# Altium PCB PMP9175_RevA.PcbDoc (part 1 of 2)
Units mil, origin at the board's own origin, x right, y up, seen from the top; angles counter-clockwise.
Board outline 3600 x 2200 mil, 4 copper layers (Top Layer, MidLayer1, MidLayer2, Bottom Layer), stack 73.2 mil thick; 114 components, 75 nets, 326 pads, 97 vias.
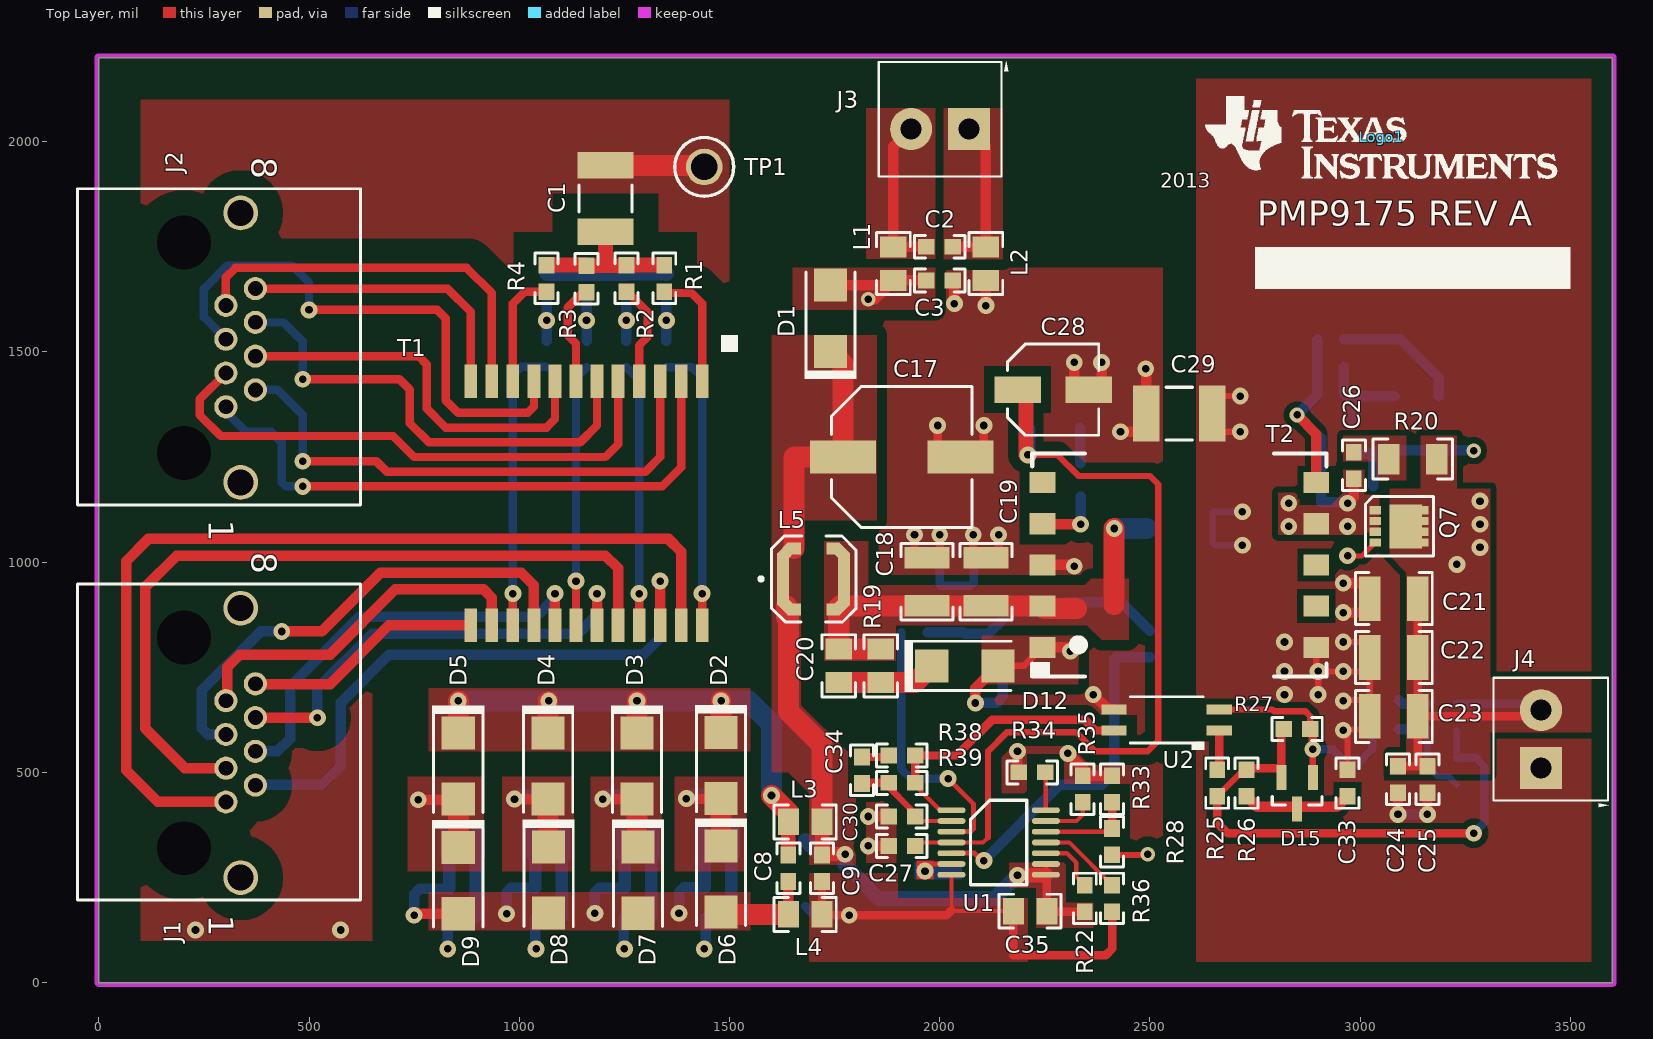
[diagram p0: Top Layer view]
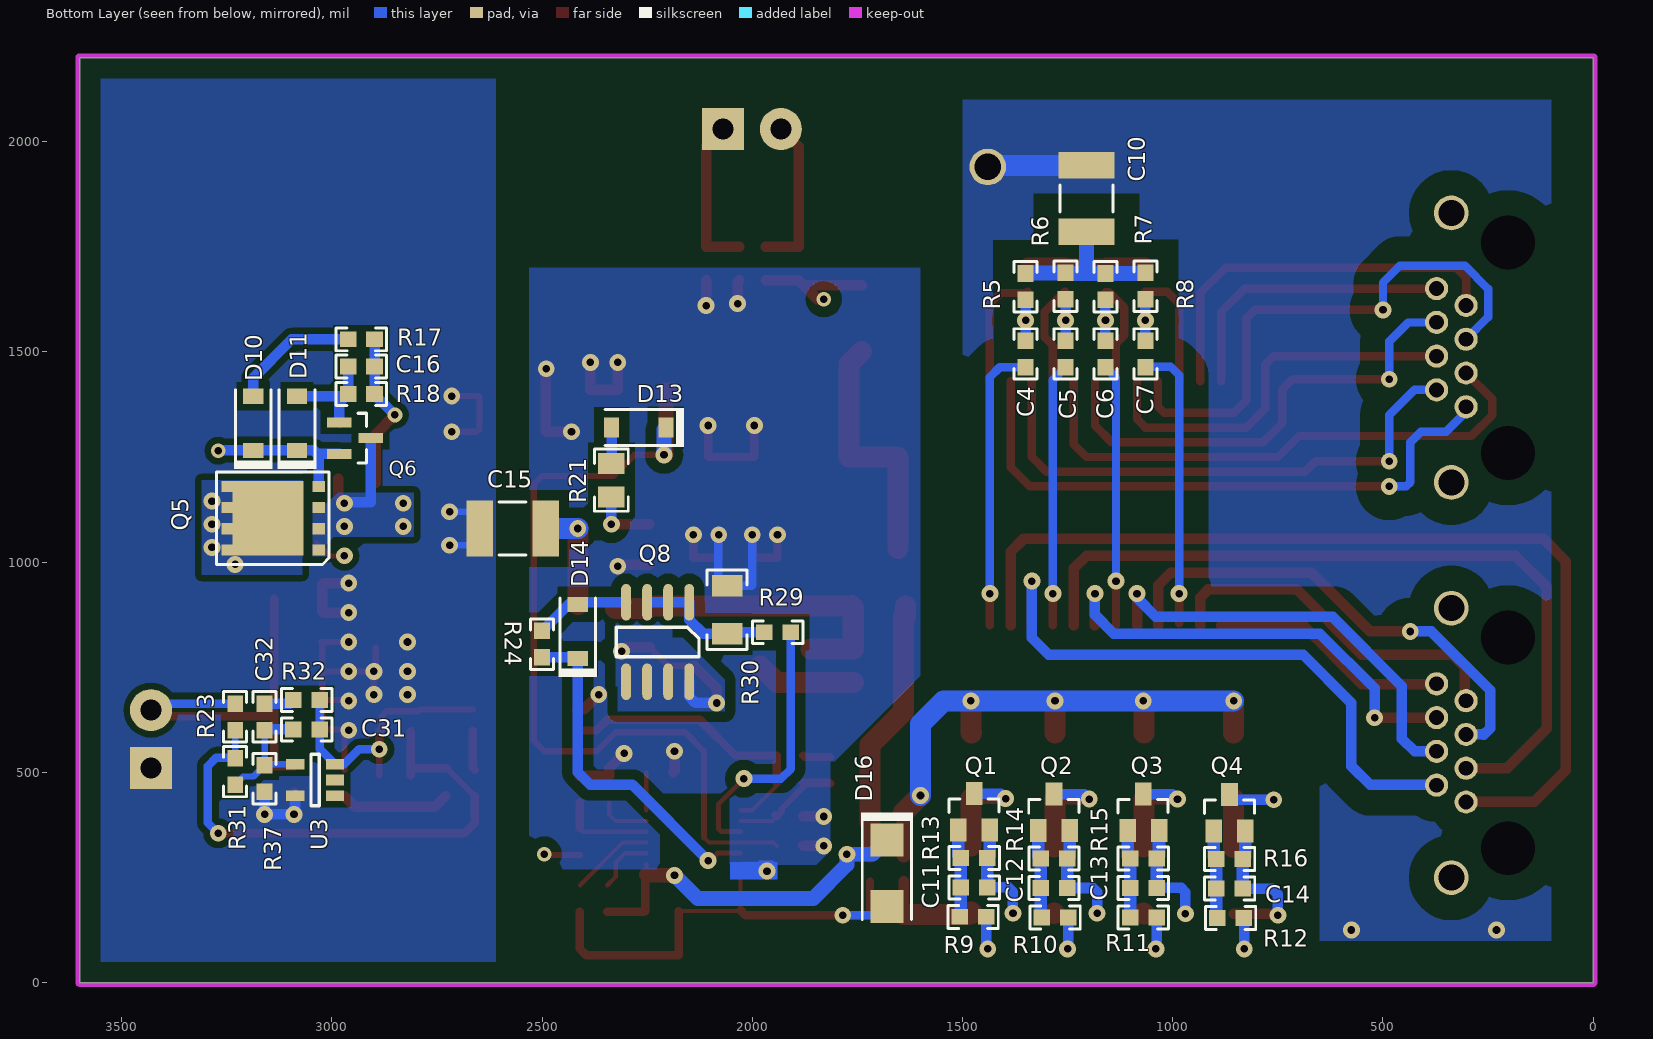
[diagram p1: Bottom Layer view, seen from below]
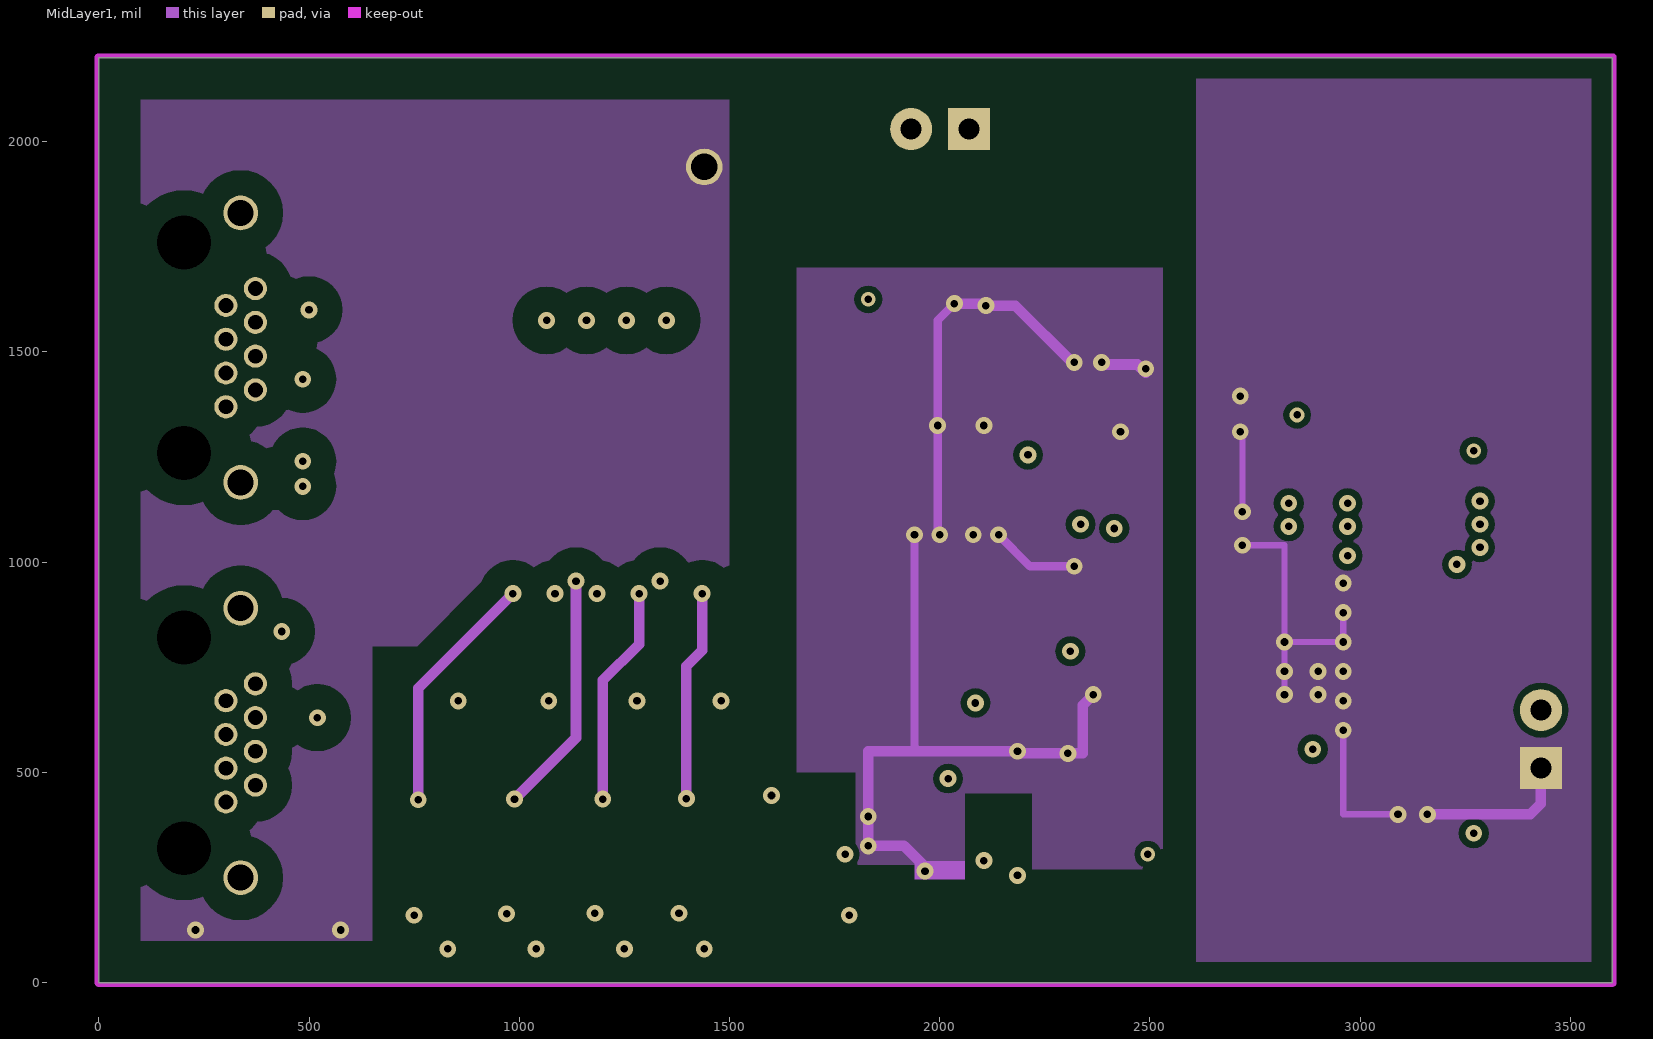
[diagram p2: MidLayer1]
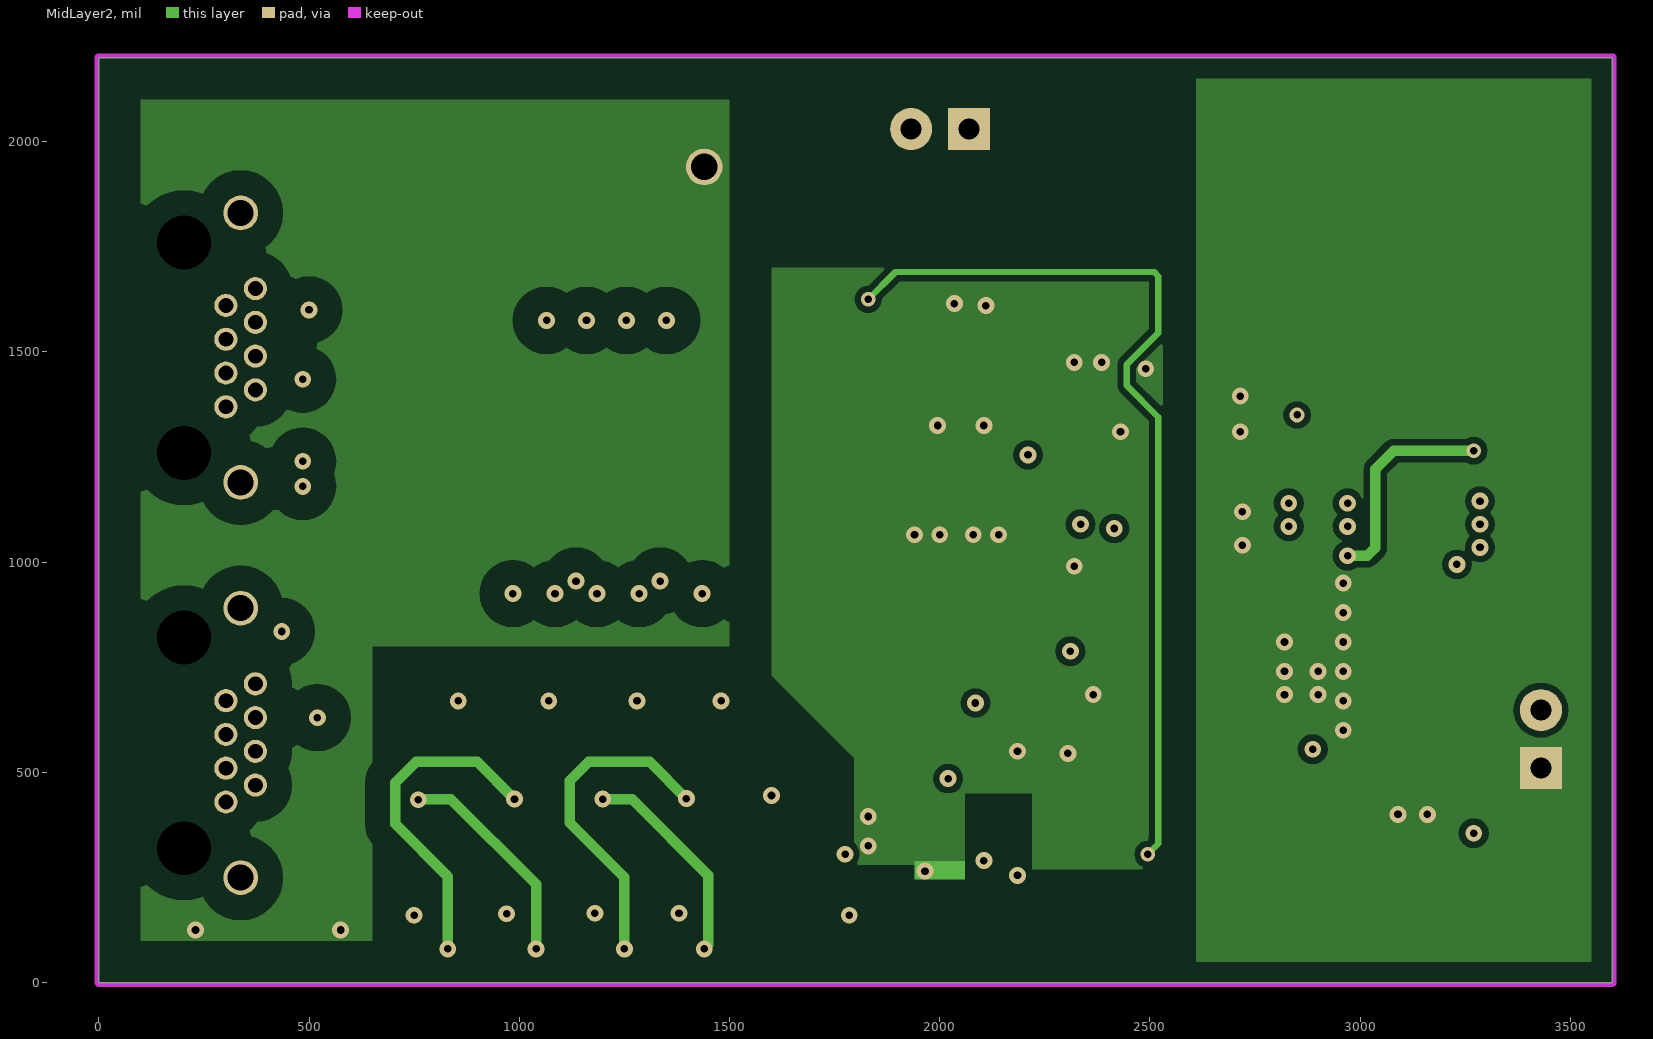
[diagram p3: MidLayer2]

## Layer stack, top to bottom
Top Layer: signal copper 2.8
Dielectric: core 24.7, FR-4, Dk 4.8
MidLayer1: signal copper 2.8
Dielectric: prepreg 12.6, FR-4, Dk 4.8
MidLayer2: signal copper 2.8
Dielectric: core 24.7, FR-4, Dk 4.8
Bottom Layer: signal copper 2.8

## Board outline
0,0 3600,0 3600,2200 0,2200

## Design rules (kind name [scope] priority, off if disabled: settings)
AcuteAngle [All] p1: minimum=4.50000000000000E+0001 checktracksonly=FALSE
AssemblyTestPointUsage [All] p1: valid=2
Clearance Clearance_9 [InNamedPolygon('MidLayer2-EARTH')] p1: gap=60
Clearance Clearance_8 [InNamedPolygon('MidLayer1-EARTH')] p2: gap=60
Clearance Clearance_7 [InNamedPolygon('Bottom Layer-EARTH')] p3: gap=60
Clearance Clearance_6 [InNamedPolygon('Top Layer-EARTH')] p4: gap=60
Clearance Clearance_5 [InNamedPolygon('Bottom Layer-PWRGND')] p5: gap=25
Clearance Clearance_4 [InNamedPolygon('Top Layer-PWRGND')] p6: gap=25
Clearance Clearance_3 [InNamedPolygon('Top Layer-No Net 10')] p7: gap=25
Clearance Clearance_2 [InNamedPolygon('Bottom Layer-EARTH')] p8: gap=60
Clearance Clearance_1 [InNamedPolygon('Top Layer-Earth')] p9: gap=60
Clearance Clearance_BoardEdge_MountingHoles [OnCopper and InComponentClass('Mounting Holes') vs IsKeepOut] p10: gap=25
Clearance Clearance_BoardEdge_Poly [OnCopper and InPoly vs IsKeepOut] p11: gap=25
Clearance Clearance_BoardEdge [OnCopper and Not InComponentClass('Logo') and not InComponentClass('FiducialMark') and not InRegion(1000,500,4000,800) and Not IsKeepout vs IsKeepOut] p12: gap=25
Clearance Clearance_Poly [InPolygon] p13: gap=15
Clearance [All] p14: gap=8
ComponentClearance ComponentClearance_Logo [InComponentClass('Logo')] p1: gap=10 collisioncheckmode=3 verticalgap=10 showdistances=FALSE
ComponentClearance ComponentClearance_ScrewToNut [(HasFootprint('NY PMS 440 0025 PH')) vs (HasFootprint('Keystone_1902C'))] p2: gap=5 collisioncheckmode=3 verticalgap=10 showdistances=FALSE
ComponentClearance ComponentClearance_MountingHoles [InComponentClass('Mounting Holes')] p3: gap=25 collisioncheckmode=3 verticalgap=100000 showdistances=FALSE
ComponentClearance ComponentClearance_SmallPassives [HasFootprint('0201*') or HasFootprint('0402*') or HasFootprint('0508') or HasFootprint('0603*') or HasFootprint('0612') or HasFootprint('0805*') or HasFootprint('0815*') or HasFootprint('0830*') or HasFootprint('1206*') or HasFootprint('1210*') or HasFootprint('1808*') or HasFootprint('1812*') or HasFootprint('1825*') or HasFootprint('2010*') or HasFootprint('2220*') or HasFootprint('2225*') or HasFootprint('2512*') or HasFootprint('2728*') or HasFootprint('3518*') vs HasFootprint('0201*') or HasFootprint('0402*') or HasFootprint('0508') or HasFootprint('0603*') or HasFootprint('0612') or HasFootprint('0805*') or HasFootprint('0815*') or HasFootprint('0830*') or HasFootprint('1206*') or HasFootprint('1210*') or HasFootprint('1808*') or HasFootprint('1812*') or HasFootprint('1825*') or HasFootprint('2010*') or HasFootprint('2220*') or HasFootprint('2225*') or HasFootprint('2512*') or HasFootprint('2728*') or HasFootprint('3518*')] p4: gap=5 collisioncheckmode=3 verticalgap=10 showdistances=FALSE
ComponentClearance ComponentClearance_THtoSMT [IsThruComponent vs IsSMTComponent] p5: gap=10 collisioncheckmode=3 verticalgap=30 showdistances=FALSE
ComponentClearance ComponentClearance_THtoTH [IsThruComponent vs IsThruComponent] p6: gap=10 collisioncheckmode=3 verticalgap=30 showdistances=FALSE
ComponentClearance [All] p7: gap=5 collisioncheckmode=3 verticalgap=10 showdistances=FALSE
DiffPairsRouting [All] p1: maxlimit=100 minlimit=10 mostfreqgap=10 maxuncoupledlength=1000
FabricationTestPointUsage TestPointUsage [All] p1: valid=2 allowmultiple=FALSE
FabricationTestpoint Testpoint [All] p1: side=3 testpointundercomponent=TRUE minsize=40 maxsize=100 preferedsize=60 minholesize=0 maxholesize=40 preferedholesize=32 testpointgrid=1 allowsidetop=TRUE allowsidebottom=TRUE usegrid=TRUE gridtolerance=0.01
FanoutControl Fanout_LCC [IsLCC] p1: bgadir=Out bgaviamode=Centered fanoutstyle=Auto fanoutdirection=Alternating viagrid=1 // Fanout_LCC (Default Rule)
FanoutControl Fanout_BGA [IsBGA] p2: bgadir=Out bgaviamode=Centered fanoutstyle=Auto fanoutdirection=Alternating viagrid=1 // Fanout_BGA (Default Rule)
FanoutControl Fanout_Default [All] p4: bgadir=Out bgaviamode=Centered fanoutstyle=Auto fanoutdirection=Alternating viagrid=1 // Fanout_Default (Default Rule)
FanoutControl Fanout_Small [(CompPinCount < 5)] p5: bgadir=Out bgaviamode=Centered fanoutstyle=Auto fanoutdirection=OutThenIn viagrid=1 // Fanout_Small (Default Rule)
HoleSize [All] p1: absolutevalues=TRUE maxlimit=251 minlimit=6 maxpercent=80.000 minpercent=20.000
MinimumAnnularRing MinimumAnnularRing_ThermalPadVias [IsVia and InAnyComponent] p1: minimumring=5.91
MinimumAnnularRing [All] p2: minimumring=7
MinimumSolderMaskSliver MinimumSolderMaskSliver_Logo [InComponentClass('Logo') vs InComponentClass('Logo')] p1: minsoldermaskwidth=0.7
MinimumSolderMaskSliver [All] p2: minsoldermaskwidth=2
PlaneClearance [All] p1: clearance=12
PlaneConnect [All] p1: planeconnectstyle=Direct reliefexpansion=10 reliefentries=4 reliefconductorwidth=10 reliefairgap=10
PolygonConnect [All] p1: connectstyle=Direct reliefconductorwidth=10 reliefentries=4 polygonreliefangle="90 Angle" airgapwidth=10
RoutingCorners [All] p1: cornerstyle=45-Degree minsetback=0.1 maxsetback=0.2
RoutingVias ThermalPadVias [IsVia and InAnyComponent] p1: holewidth=7.87 width=19.68 viastyle="Through Hole" minholewidth=7.87 minwidth=19.68 maxholewidth=12.99 maxwidth=23.62
RoutingVias [All] p2: holewidth=18 width=35 viastyle="Through Hole" minholewidth=6 minwidth=20 maxholewidth=24 maxwidth=50
SMDToCorner [All] p1: distance=1000
SilkToSilkClearance [All] p1: silktosilkclearance=0.1
SilkscreenOverComponentPads [All] p1: minsilkscreentomaskgap=0.1
SolderMaskExpansion [All] p1: expansion=2
Width [All] p1: maxlimit=100 minlimit=6 preferedwidth=10 checkconnectedcopper=TRUE
12 further rules are at their usual default settings.

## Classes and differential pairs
component class Logo: Logo1
component class PMP9175_RevA_SH1: 40 C1 C2 C3 C4 C5 C6 C7 C8 C9 C10 C11 C12 C13 C14 D1 D2 D3 D4 D5 D6 D7 D8 D9 J1 J2 J3 L1 L2 L3 L4 Logo1 Q1 Q2 Q3 Q4 R1 R2 R3 R4 R5 R6 R7 R8 R9 R10 R11 R12 R13 R14 R15 R16 T1 TP1
component class PMP9175_RevA_SH2: 40 C15 C16 C17 C18 C19 C20 C21 C22 C23 C24 C25 C26 C27 C28 C29 C30 C31 C32 C33 C34 C35 D10 D11 D12 D13 D14 D15 D16 J4 L5 Q5 Q6 Q7 Q8 R17 R18 R19 R20 R21 R22 R23 R24 R25 R26 R27 R28 R29 R30 R31 R32 R33 R34 R35 R36 R37 R38 R39 R40 T2 U1 U2 U3

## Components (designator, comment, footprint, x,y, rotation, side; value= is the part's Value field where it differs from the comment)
C1 "1812GC102KA1" 1812 1205,1865 r90 top
C2 "C1608X7R2A102K" 0603 2000,1750 r0 top
C3 "C1608X7R2A102K" 0603 2000,1670 r0 top
C4 "C1608X7R2A103K" 0603 1350,1495 r90 bottom
C5 "C1608X7R2A103K" 0603 1255,1495 r90 bottom
C6 "C1608X7R2A103K" 0603 1160,1495 r90 bottom
C7 "C1608X7R2A103K" 0603 1065,1495 r90 bottom
C8 "C1608X7R2A102K" 0603 1640,271.95 r270 top
C9 "C1608X7R2A102K" 0603 1720,271.95 r270 top
C10 "1812GC102KA1" 1812 1205,1865 r90 bottom
C11 "C1608C0G1H331J" 0603 1472.45,226.18 r180 bottom
C12 "C1608C0G1H331J" 0603 1282.45,224.92 r180 bottom
C13 "C1608C0G1H331J" 0603 1070,225.08 r180 bottom
C14 "C1608C0G1H331J" 0603 865,223.7 r180 bottom
C15 "C4532X7R3D222K" 1812 2570,1080 r180 bottom
C16 "C1608C0G1H471J" 0603 2930,1465 r180 bottom
C17 "EEE-FK2A220P" SM_RADIAL_F 1910,1250 r0 top
C18 "GRM32ER72A225KA35L" 1210 1969.92,953.23 r90 top
C19 "GRM32ER72A225KA35L" 1210 2109.92,953.23 r90 top
C20 "C2012X7R2A104K" 0805_HV 1759.92,753.23 r270 top
C21 "C3225X5R0J107M" 1210 3080.24,913.23 r180 top
C22 "C3225X5R0J107M" 1210 3080.24,773.23 r180 top
C23 "C3225X5R0J107M" 1210 3080.24,633.23 r180 top
C24 "C1608X7R1C105K" 0603 3089.92,483.23 r270 top
C25 "C1608X7R1H104K" 0603 3159.92,483.23 r270 top
C26 "C1608X7R1H222K" 0603 2985,1230 r270 top
C27 "C1608X7R1C105K" 0603 1910,325 r180 top
C28 "EEE-FK1C220R" SM_RADIAL_C 2270,1410 r0 top
C29 "C4532X7R3D222K" 1812 2569.92,1353.23 r180 top
C30 "C1608X7R1H104K" 0603 1910,395 r180 top
C31 "C1608C0G1H101J" 0603 3059.92,601.93 r180 bottom
C32 "GRM188R71H682KA01D" 0603 3159.92,631.93 r90 bottom
C33 "C1608X7R1C105K" 0603 2969.92,474.53 r90 top
C34 "C1608X7R1E473K" 0603 1815,505 r90 top
C35 "C2012X7R2A104K" 0805_HV 2215,170 r180 top
D1 "B1100-13-F" SMA 1740,1580 r90 top
D2 "B1100-13-F" SMA 1480,516.26 r270 top
D3 "B1100-13-F" SMA 1280,515 r270 top
D4 "B1100-13-F" SMA 1068.7,515.08 r270 top
D5 "B1100-13-F" SMA 855,515 r270 top
D6 "B1100-13-F" SMA 1480,246.26 r270 top
D7 "B1100-13-F" SMA 1282.45,243.62 r270 top
D8 "B1100-13-F" SMA 1070,243.78 r270 top
D9 "B1100-13-F" SMA 855,242.4 r270 top
D10 "MMSD4148T1G" SOD-123 3187.09,1330 r90 bottom
D11 "MMSD4148T1G" SOD-123 3082.78,1330 r90 bottom
D12 "MURA120T3G" SMA 2059.92,753.23 r0 top
D13 "MMSD4148T1G" SOD-123 2270,1320 r0 bottom
D14 "MMSD4148T1G" SOD-123 2415,835 r90 bottom
D15 "BAT54S-7-F" SOT-23 2850,450 r270 top
D16 "SMAJ58A" SMA 1680,260 r270 bottom
J1 "1-406541-1" 1-406541-1 280,570 r270 top
J2 "1-406541-1" 1-406541-1 280,1510 r270 top
J3 "ED555/2DS" TERM_BLK_ED555-2DS 2070,2030 r180 top
J4 "ED555/2DS" TERM_BLK_ED555-2DS 3430,510 r90 top
L1 "MMZ2012R300A" 0805_HV 1890,1710 r270 top
L2 "MMZ2012R300A" 0805_HV 2110,1710 r270 top
L3 "MMZ2012R300A" 0805_HV 1680,381.95 r0 top
L4 "MMZ2012R300A" 0805_HV 1680,161.95 r0 top
L5 "LPS4018-332MLB" LPS4018 1700,960 r0 top
Logo1 "Texas Instruments" TI_Stacked_Overlay_Small 3050,2010 r0 top
Q1 "FDN8601" SSOT-3 1472.45,406.18 r180 bottom
Q2 "FDN8601" SSOT-3 1282.45,404.92 r180 bottom
Q3 "FDN8601" SSOT-3 1070,405 r180 bottom
Q4 "FDN8601" SSOT-3 865,403.7 r180 bottom
Q5 "CSD17527Q5A" TRANS_NexFET_Q5A 3140.35,1104.49 r0 bottom
Q6 "MMBT3906" SOT-23 2945,1295 r180 bottom
Q7 "CSD17551Q3A" TRANS_NexFET_Q3A 3100,1085 r0 top
Q8 "FDS86242" SOIC-8 2225,810 r270 bottom
R1 "CRCW060375R0FKEA" 0603 1345,1675 r90 top
R2 "CRCW060375R0FKEA" 0603 1255,1675 r90 top
R3 "CRCW060375R0FKEA" 0603 1160,1673.7 r90 top
R4 "CRCW060375R0FKEA" 0603 1065,1675 r90 top
R5 "CRCW060375R0FKEA" 0603 1350,1655 r270 bottom
R6 "CRCW060375R0FKEA" 0603 1255,1656.3 r270 bottom
R7 "CRCW060375R0FKEA" 0603 1160,1655 r270 bottom
R8 "CRCW060375R0FKEA" 0603 1065,1656.3 r270 bottom
R9 "CRCW0603499KFKEA" 0603 1475,156.26 r180 bottom
R10 "CRCW0603499KFKEA" 0603 1280,155 r180 bottom
R11 "CRCW0603499KFKEA" 0603 1070,155 r180 bottom
R12 "CRCW0603499KFKEA" 0603 862.55,153.78 r180 bottom
R13 "CRCW0603150KFKEA" 0603 1472.45,296.18 r0 bottom
R14 "CRCW0603150KFKEA" 0603 1282.45,294.92 r0 bottom
R15 "CRCW0603150KFKEA" 0603 1070,295.08 r0 bottom
R16 "CRCW0603150KFKEA" 0603 865,293.7 r0 bottom
R17 "CRCW060310R0JNEA" 0603 2930,1530 r0 bottom
R18 "CRCW06034K99FKEA" 0603 2930,1400 r0 bottom
R19 "CRCW080539K0JNEA" 0805_HV 1859.92,753.23 r90 top
R20 "CRCW12063R30JNEA" 1206 3125.28,1245 r0 top
R21 "CRCW080520R0JNEA" 0805_HV 2335,1195 r270 bottom
R22 "CRCW060327K4FKEA" 0603 2345,200 r270 top
R23 "ERJ-3GEY0R00V" 0603 3229.92,631.93 r90 bottom
R24 "CRCW060310R0JNEA" 0603 2500,805 r90 bottom
R25 "CRCW0603681RFKEA" 0603 2659.92,474.53 r270 top
R26 "CRCW060310K0FKEA" 0603 2729.92,474.53 r90 top
R27 "CRCW06032K00FKEA" 0603 2849.92,603.23 r180 top
R28 "CRCW0603392KFKEA" 0603 2410,335 r270 top
R29 "CRCW06031K00FKEA" 0603 1939.92,833.23 r0 bottom
R30 "STD" 1206 2059.92,886.3 r270 bottom
R31 "CRCW060344K2FKEA" 0603 3229.92,501.93 r90 bottom
R32 "CRCW06031K00FKEA" 0603 3059.92,671.93 r180 bottom
R33 "CRCW060320K5FKEA" 0603 2410,460 r270 top
R34 "CRCW060359K0FKEA" 0603 2220,500 r0 top
R35 "CRCW060380K6FKEA" 0603 2340,460 r270 top
R36 "CRCW060390R9FKEA" 0603 2410,200 r90 top
R37 "CRCW060314K3FKEA" 0603 3159.92,485 r90 bottom
R38 "CRCW06031K00FKEA" 0603 1910,540 r180 top
R39 "CRCW06032K00FKEA" 0603 1910,475 r180 top
T1 "H6062" S0-24_500MIL 1160,1140 r270 top
T2 "PA6340-AL" Coilcraft_PA6340-AL 2569.92,993.23 r90 top
TP1 "5012" Keystone5012 1440,1940 r90 top
U1 "TPS23753APW" PW0014A_N 2140.24,333.23 r0 top
U2 "HMHA2801A" MFP04A 2539.92,624.53 r180 top
U3 "TLV431AIDBV" DBV0005A_N 3039.92,481.93 r0 bottom

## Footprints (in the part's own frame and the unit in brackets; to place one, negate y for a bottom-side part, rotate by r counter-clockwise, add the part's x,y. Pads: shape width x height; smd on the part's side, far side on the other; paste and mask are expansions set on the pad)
1-406541-1 [mm] "Connector; PCB Jack, Thru-Hole; 1-Port, 8 Positions, 8 Loaded; Shielded without LEDs; Right Angle"
  round 1.4 hole 0.89: 1(3.57,0.57) 2(2.55,2.35) 3(1.53,0.57) 4(0.51,2.35) 5(-0.51,0.57) 6(-1.53,2.35) 7(-2.55,0.57) 8(-3.57,2.35)
  round 2.1 hole 1.57 unplated: MH1(8.14,1.46) MH4(-8.14,1.46)
  round 2.95 hole 3.25 unplated: MH2(6.36,-1.97) MH3(-6.36,-1.97)
  silkscreen extent -9.6,-8.4 9.5,8.7, body extent -9.31,-7.25 9.33,8.5, height 14.23
0603 [mm] "0603 from SM-752 data"
  rect 1x0.95 smd: 1(-0.8,0) 2(0.8,0)
  silkscreen extent -1.52,-0.69 1.52,0.69, body extent -0.87,-0.47 0.87,0.47, height 0.85
0805_HV [mil] "0805 with 30mil clearance between pads"
  rect 50x63 smd: 1(-40,0) 2(40,0)
  silkscreen extent -74,-40 74,40, body extent -43,-29 43,29, height 43
1206 [mm] "1206 from SM-752 data"
  rect 1.3x1.85 smd: 1(-1.45,0) 2(1.45,0)
  silkscreen extent -2.4,-1.21 2.4,1.21, body extent -1.7,-0.9 1.7,0.9, height 1.35
1210 [mm] "1210 from SM-752 data"
  rect 1.3x2.7 smd: 1(-1.45,0) 2(1.45,0)
  silkscreen extent -2.32,-1.57 2.32,1.57, body extent -1.7,-1.35 1.7,1.35, height 1.35
1812 [mm]
  rect 1.6x3.4 smd: 1(-2,0) 2(2,0)
  silkscreen extent -0.8,-1.6 0.8,1.6, body extent -2.4,-1.7 2.4,1.7, height 1.35
Coilcraft_PA6340-AL [mil] "Coilcraft"
  rect 50x61 smd: 1(-196,325.5) 2(-98,325.5) 3(0,325.5) 4(98,325.5) 5(196,325.5) 6(196,-325.5) 7(98,-325.5) 8(0,-325.5) 9(-98,-325.5) 10(-196,-325.5)
  silkscreen extent -265,-350 265,350, body extent -266,-276 265,279, height 504
DBV0005A_N [mm] "SOT23, 5-Leads, Body 2.9x1.6mm, Pitch 0.95mm, Lead Span 2.8mm, IPC Medium Density"
  rect 1.1x0.65 smd: 1(-1.2,0.95) 2(-1.2,0) 3(-1.2,-0.95) 4(1.2,-0.95) 5(1.2,0.95)
  silkscreen extent -0.25,-1.55 0.25,1.55, body extent -1.42,-1.46 1.42,1.46, height 1.08
Keystone5012 [mil] "Keystone Multipurpose loops"
  round 87 hole 63: 1(0,0)
  silkscreen extent -70,-70 70,70, body extent -63,-63 63,62, height 319
LPS4018 [mil]
  rect 28x123 smd: 1(-72.5,0) 2(72.5,0)
  rect 35.5x28 smd rot 135: 1(-64,-64) 2(64,64)
  rect 35.5x28 smd rot 45: 1(-64,64) 2(64.5,-63.5)
  rect 31.5x28 smd: 1(-46,-72.5) 1(-46,72.5) 2(46,-72.5) 2(46,72.5)
  silkscreen extent -129,-102 100,102, body extent -81,-81 81,81, height 71
MFP04A [mm] "FAIRCHILD optocoupler"
  rect 1.52x0.61 smd: 1(-3.175,0.635) 2(-3.175,-0.635) 3(3.175,-0.635) 4(3.175,0.635)
  silkscreen extent -2.28,-1.4 2.2,1.8, body extent -3.6,-1.34 3.6,1.34, height 2.39
PW0014A_N [mm] "TSOP, 14-Leads, Body 5x4.4mm, Pitch 0.65mm, IPC Medium Density"
  oval 1.7x0.35 smd: 1(-2.85,1.95) 2(-2.85,1.3) 3(-2.85,0.65) 4(-2.85,0) 5(-2.85,-0.65) 6(-2.85,-1.3) 7(-2.85,-1.95) 8(2.85,-1.95) 9(2.85,-1.3) 10(2.85,-0.65) 11(2.85,0) 12(2.85,0.65) 13(2.85,1.3) 14(2.85,1.95)
  silkscreen extent -1.7,-2.55 1.7,2.55, body extent -3.21,-2.5 3.21,2.5, height 0.98
S0-24_500MIL [mil]
  rect 80x30 smd: 1(-290,275) 2(-290,225) 3(-290,175) 4(-290,125) 5(-290,75) 6(-290,25) 7(-290,-25) 8(-290,-75) 9(-290,-125) 10(-290,-175) 11(-290,-225) 12(-290,-275) 13(290,-275) 14(290,-225) 15(290,-175) 16(290,-125) 17(290,-75) 18(290,-25) 19(290,25) 20(290,75) 21(290,125) 22(290,175) 23(290,225) 24(290,275)
  silkscreen extent -400,320 -360,360
SM_RADIAL_C [mm] "5 x 5.8mm:  Panasonic C"
  rect 2.8x1.6 smd: 1(-2.15,0) 2(2.15,0)
  silkscreen extent -2.75,-2.75 2.75,2.75, body extent -2.76,-2.76 2.76,2.76, height 6.1
SM_RADIAL_F [mm] "8 x 10.2mm:  Panasonic F"
  rect 4x2 smd: 1(-3.55,0) 2(3.55,0)
  silkscreen extent -4.25,-4.25 4.25,4.25, body extent -4.26,-4.26 4.26,4.26, height 10.5
SMA [mm] "Molded Diode, 2-Leads, Body 4.3x2.6mm, IPC Medium Density, based on OnSemi component dimensions and land pattern"
  rect 2x2 smd: 1(-2,0) 2(2,0)
  silkscreen extent -3.66,-1.57 2.79,1.57, body extent -2.6,-1.3 2.6,1.3, height 2.42
SOD-123 [mm] "On Semi recommended land pattern"
  rect 0.915x1.22 smd: 1(-1.637,0) 2(1.637,0)
  silkscreen extent -2.74,-1.17 2.03,1.17, body extent -1.93,-0.9 1.93,0.9, height 1.35
SOIC-8 [mm] "duplicate of SO-8.  SOIC, 8-Leads, Body 5.0x4.0mm (max), Pitch 1.27mm, IPC Medium Density"
  oval 2.2x0.6 smd: 1(-2.4,1.905) 2(-2.4,0.635) 3(-2.4,-0.635) 4(-2.4,-1.905) 5(2.4,-1.905) 6(2.4,-0.635) 7(2.4,0.635) 8(2.4,1.905)
  silkscreen extent -0.9,-2.5 0.9,2.5, body extent -3,-2.45 3,2.45, height 1.63
SOT-23 [mm] "SOT23, 3-Leads, Body 2.9x1.3mm, Pitch 0.95mm, Lead Span 2.5mm, IPC Medium Density"
  rect 1.5x0.6 smd: 1(-0.95,0.95) 2(-0.95,-0.95) 3(0.95,0)
  silkscreen extent 0.2,-1.5 0.7,1.5, body extent -1.16,-1.45 1.21,1.45, height 1
SSOT-3 [mm] "SuperSOT-3"
  rect 1x1.4 smd: 1(-0.95,-1.1) 2(0.95,-1.1) 3(0,1.1)
  silkscreen extent -1.53,-0.05 1.5,0.77, body extent -1.52,-0.76 1.52,0.76, height 1.12
TERM_BLK_ED555-2DS [mil]
  rect 100x100 hole 50: 1(0,0)
  round 100 hole 50: 2(138,0)
  silkscreen extent -93,-161 215,113, body extent -69,-150 207,106, height 323
TI_Stacked_Overlay_Small [mil]
  silkscreen extent -418,-98 418,98
TRANS_NexFET_Q3A [mm] "TI"
  rect 0.68x0.5 smd paste-1 mask+0.076: 1(-1.625,0.975) 2(-1.625,0.325) 3(-1.625,-0.325) 4(-1.625,-0.975)
  rect 0.41x0.5 smd paste-1 mask+0.076: 5(1.385,-0.975) 6(1.385,-0.325) 7(1.385,0.325) 8(1.385,0.975)
  rect 1.96x2.65 smd paste-3 mask+0.076: 9(0.205,0)
  Top Layer region: 1.18,-1.325 1.24,-1.325 1.24,-1.225 1.18,-1.225
  Top Layer region: 1.18,1.225 1.24,1.225 1.24,1.325 1.18,1.325
  silkscreen extent -2.21,-1.8 1.9,1.8, body extent -1.55,-1.62 1.55,1.62, height 0.91
TRANS_NexFET_Q5A [mm] "TI recommended land pattern (nominal) M0139-01"
  rect 0.75x0.675 smd paste-0.1 mask+0.051: 1(-2.776,1.917) 2(-2.776,0.639) 3(-2.776,-0.639) 4(-2.776,-1.917)
  rect 0.655x0.675 smd paste-0.1 mask+0.051: 5(2.776,-1.917) 6(2.776,-0.639) 7(2.776,0.639) 8(2.776,1.917)
  rect 4.295x4.51 smd paste-2.2 mask+0.051: 9(0.301,0)
  silkscreen extent -3.4,-2.8 3.4,2.8, body extent -3.05,-2.5 3.05,2.5, height 1.11

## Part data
C1 C10: "CAP, CERM, 1000pF, 2000V, +/-10%, X7R, 1812"
C2 C3 C8 C9: "CAP, CERM, 1000pF, 100V, +/-10%, X7R, 0603"
C4 C5 C6 C7: "CAP, CERM, 0.01uF, 100V, +/-10%, X7R, 0603"
C11 C12 C13 C14: "CAP, CERM, 330pF, 50V, +/-5%, C0G/NP0, 0603"
C15 C29: "CAP, CERM, 2200pF, 2000V, +/-10%, X7R, 1812"
C16: "CAP, CERM, 470pF, 50V, +/-5%, C0G/NP0, 0603"
C17: "CAP, AL, 22uF, 100V, +/-20%, 1.3 ohm, SMD"
C18 C19: "CAP, CERM, 2.2uF, 100V, +/-10%, X7R, 1210"
C20 C35: "CAP, CERM, 0.1uF, 100V, +/-10%, X7R, 0805"
C21 C22 C23: "CAP, CERM, 100uF, 6.3V, +/-20%, X5R, 1210"
C24 C27 C33: "CAP, CERM, 1uF, 16V, +/-10%, X7R, 0603"
C25 C30: "CAP, CERM, 0.1uF, 50V, +/-10%, X7R, 0603"
C26: "CAP, CERM, 2200pF, 50V, +/-10%, X7R, 0603"
C28: "CAP, AL, 22uF, 16V, +/-20%, 0.7 ohm, SMD"
C31: "CAP, CERM, 100pF, 50V, +/-5%, C0G/NP0, 0603"
C32: "CAP, CERM, 6800pF, 50V, +/-10%, X7R, 0603"
C34: "CAP, CERM, 0.047uF, 25V, +/-10%, X7R, 0603"
D1 D2 D3 D4 D5 D6 D7 D8 D9: "Diode, Schottky, 100V, 1A, SMA"
D10 D11 D13 D14: "Diode, Switching, 100V, 0.2A, SOD-123"
D12: "Diode, Ultrafast, 200V, 1A, SMA"
D15: "Diode, Schottky, 30V, 0.2A, SOT-23"
D16: "Diode, TVS, Uni, 58V, 400W, SMA"
J1 J2: "RJ-45, Right Angle, No LED, tab up"
J3 J4: "Terminal Block, 6A, 3.5mm Pitch, 2-Pos, TH"
L1 L2 L3 L4: "1.5A Ferrite Bead, 30 ohm @ 100MHz, SMD"
L5: "Inductor, Shielded Drum Core, Ferrite, 3.3uH, 1.9A, 0.08 ohm, SMD"
Logo1: library part TI_Logo, "Texas Instrument Corporate Signature"
Q1 Q2 Q3 Q4: "MOSFET, N-CH, 100V, 2.7A, SSOT-3"
Q5: "MOSFET, N-CH, 30V, 65A, SON 5x6mm"
Q6: library part "MMBT3906, Fairchild Semiconductor", "Transistor, PNP, 40V, 0.2A, SOT-23"
Q7: "MOSFET, N-CH, 30V, 12A, SON 3.3x3.3mm"
Q8: "MOSFET, N-CH, 150V, 4.1A, SOIC-8"
R1 R2 R3 R4 R5 R6 R7 R8: "RES, 75.0 ohm, 1%, 0.1W, 0603"
R9 R10 R11 R12: "RES, 499k ohm, 1%, 0.1W, 0603"
R13 R14 R15 R16: "RES, 150k ohm, 1%, 0.1W, 0603"
R17 R24: "RES, 10 ohm, 5%, 0.1W, 0603"
R18: "RES, 4.99k ohm, 1%, 0.1W, 0603"
R19: "RES, 39k ohm, 5%, 0.125W, 0805"
R20: "RES, 3.3 ohm, 5%, 0.25W, 1206"
R21: "RES, 20 ohm, 5%, 0.125W, 0805"
R22: "RES, 27.4k ohm, 1%, 0.1W, 0603"
R23: "RES, 0 ohm, 5%, 0.1W, 0603"
R25: "RES, 681 ohm, 1%, 0.1W, 0603"
R26: "RES, 10.0k ohm, 1%, 0.1W, 0603"
R27 R39: "RES, 2.00k ohm, 1%, 0.1W, 0603"
R28: "RES, 392k ohm, 1%, 0.1W, 0603"
R29 R32 R38: "RES, 1.00k ohm, 1%, 0.1W, 0603"
R30: library part ERJ-8RQF1R0V, "RES, 0.5 ohm, 1%, 0.25W, 1206"
R31: "RES, 44.2k ohm, 1%, 0.1W, 0603"
R33: "RES, 20.5k ohm, 1%, 0.1W, 0603"
R34: "RES, 59.0k ohm, 1%, 0.1W, 0603"
R35: "RES, 80.6k ohm, 1%, 0.1W, 0603"
R36: "RES, 90.9 ohm, 1%, 0.1W, 0603"
R37: "RES, 14.3k ohm, 1%, 0.1W, 0603"
T1: library part XFMR_H6062, "Transformer,"
T2: "Transformer, 142uH, SMT"
TP1: "Test Point, Multipurpose, White, TH"
U1: "IEEE 802.3 PoE INTERFACE AND CONVERTER CONTROLLER WITH ENHANCED ESD IMMUNITY, PW0014A"
U2: "Optocoupler, 3.75kV RMS, SMT"
U3: "LOW-VOLTAGE ADJUSTABLE PRECISION SHUNT REGULATOR, DBV0005A"

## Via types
v1: diameter 40, hole 18, Top Layer to Bottom Layer, 93 vias
v2: diameter 35, hole 18, Top Layer to Bottom Layer, 4 vias

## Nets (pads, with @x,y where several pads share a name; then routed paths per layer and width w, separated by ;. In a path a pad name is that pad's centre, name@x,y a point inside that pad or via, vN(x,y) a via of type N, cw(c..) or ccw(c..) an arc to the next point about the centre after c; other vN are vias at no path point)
AUX: C3.1 D1.2 L1.2 R28.2 | length 2550.1
  Top Layer w15: R28.2@2410,303.5 2493.5,303.5 v2(2495,305)
  Top Layer w25: D1.2@1740,1658.74 L1.2@1878.74,1658.74 ; v2(1830,1625) 1845,1625 L1.2@1878.74,1658.74 ; C3.1@1968.5,1670 L1.2@1890,1670 L1.2@1878.74,1658.74
  MidLayer2 w15: v2(1830,1625) 1895,1690 2510,1690 2520,1680 2520,1545 2445,1470 2445,1420 2520,1345 2520,330 v2(2495,305)
EARTH: C1.2 C10.2 TP1.1 | length 473.1
  Top Layer w50: C1.2@1205,1943.74 1436.26,1943.74 TP1.1@1440,1940
  Bottom Layer w50: C10.2@1205,1943.74 1436.26,1943.74 TP1.1@1440,1940
  other v1: 230,125 575,125
GND: C15.1 C21.2 C22.2 C23.2 C24.2 C25.2 C29.1 C33.2 J4.1 R37.1 T2.10 U3.5 | length 3192.6
  Top Layer w15: v1(2715,1310) 2655,1310 2648.66,1316.34 C29.1@2648.66,1353.23 2648.66,1393.66 2650,1395 v1(2715,1395) ; T2.10@2895.42,797.23 2895.42,744.58 v1(2900,740) ; v1(2900,685) v1(2900,740) ; v1(2960,670) 2961.93,671.93 C23.2@3023.15,671.93 ; v1(2960,810) 3025,810 3023.15,808.15 C22.2@3023.15,773.23 C22.2@3023.15,741.85 ; C33.2@2969.92,506.02 2969.92,590.08 v1(2960,600) 2961.93,601.93 3025.49,601.93 3023.15,604.27 C23.2@3023.15,633.23 C23.2@3023.15,669.59 ; v1(2900,740) v1(2960,740) C22.2@3023.15,740 ; C23.2@3023.15,669.59 C23.2@3023.15,671.93 ; C23.2@3023.15,669.59 3025.49,671.93 C23.2@3023.15,671.93 ; C23.2@3023.15,671.93 C22.2@3023.15,740 ; C22.2@3023.15,740 3025,740 C22.2@3023.15,741.85 ; C22.2@3023.15,740 C22.2@3023.15,741.85
  Top Layer w25: v1(2960,880) 3020,880 3023.15,883.15 C21.2@3023.15,913.23 3023.15,946.85 3020,950 v1(2960,950) ; C24.2@3089.92,451.73 3089.92,400.08 v1(3090,400) ; C25.2@3159.92,451.73 3159.92,400.08 v1(3160,400)
  MidLayer1 w15: v1(2720,1040) 2820,1040 v1(2820,810) ; v1(2720,1120) v1@2720,1305 ; v1(2820,685) v1(2820,740) v1(2820,810) ; v1(2960,600) 2960,400 v1(3090,400) ; v1(2960,880) v1(2960,810) v1(2820,810)
  MidLayer1 w25: v1(3160,400) 3405,400 3430,425 J4.1@3430,510
  Bottom Layer w15: v1(2720,1040) 2655,1040 2648.74,1046.26 C15.1@2648.74,1080 2648.74,1118.74 2650,1120 v1(2720,1120)
  Bottom Layer w25: U3.5@3087.17,444.53 3087.17,402.83 v1(3090,400) v1(3160,400) 3159.92,400.08 R37.1@3159.92,453.5
NetC1_1: C1.1 R1.2 R2.2 R3.2 R4.2 | length 362.1
  Top Layer w35: R4.2@1065,1706.5 1158.7,1706.5 R3.2@1160,1705.2 1205,1705.2 ; C1.1@1205,1786.26 1205,1705.2 ; R1.2@1345,1706.5 R2.2@1255,1706.5 1253.7,1705.2 1205,1705.2
NetC2_1: C2.1 J3.2 L1.1 | length 375.9
  Top Layer w25: J3.2@1932,2030 1890,1988 L1.1@1890,1750 C2.1@1968.5,1750
NetC2_2: C2.2 J3.1 L2.1 | length 375.1
  Top Layer w25: C2.2@2031.5,1750 L2.1@2110,1750 2110,1990 J3.1@2070,2030
NetC4_1: C4.1 D2.2 D6.1 Q1.3 R10.2 T1.24 | length 2334.5
  Top Layer w20: T1.24@1435,850 v1(1435,925)
  Top Layer w25: v1(1397.48,437.52) D2.2@1480,437.52
  Top Layer w50: D6.1@1480,325 D2.2@1480,437.52
  MidLayer1 w25: v1(1397.48,437.52) 1397.48,752.48 1435,790 v1(1435,925)
  MidLayer2 w25: v1(1250,80) 1250,250 1120,380 1120,480 1165,525 1310,525 v1(1397.48,437.52)
  Bottom Layer w20: C4.1@1350,1463.5 1411.5,1463.5 1435,1440 v1(1435,925) v1@1435,915
  Bottom Layer w25: R10.2@1248.5,155 1248.5,81.5 v1(1250,80) ; v1(1397.48,437.52) 1409.45,449.49 Q1.3@1472.45,449.49
NetC4_2: C4.2 R5.2 | length 97
  Bottom Layer w25: C4.2@1350,1526.5 v1(1350,1575) R5.2@1350,1623.5
NetC5_1: C5.1 D3.2 D7.1 Q2.3 R9.2 T1.21 | length 2022.4
  Top Layer w20: T1.21@1285,850 v1(1285,925)
  Top Layer w25: v1(1198.74,436.26) D3.2@1280,436.26
  Top Layer w50: D3.2@1280,436.26 1280,324.81 D7.1@1282.45,322.36
  MidLayer1 w25: v1(1198.74,436.26) 1198.74,718.74 1285,805 v1(1285,925)
  MidLayer2 w25: v1(1198.74,436.26) 1268.46,436.26 1450,254.72 1450,90 v1(1440,80)
  Bottom Layer w20: C5.1@1255,1463.5 1285,1433.5 v1(1285,925)
  Bottom Layer w25: v1(1198.74,436.26) 1210.71,448.23 Q2.3@1282.45,448.23 ; v1(1440,80) 1445,80 1443.5,81.5 R9.2@1443.5,156.26
NetC5_2: C5.2 R6.2 | length 98.3
  Bottom Layer w25: C5.2@1255,1526.5 v1(1255,1575) R6.2@1255,1624.8
NetC6_1: C6.1 D4.2 D8.1 Q3.3 R12.2 T1.18 | length 2346
  Top Layer w20: T1.18@1135,850 v1(1135,955)
  Top Layer w25: v1(988.66,436.34) D4.2@1068.7,436.34
  Top Layer w50: D4.2@1068.7,436.34 1068.7,323.82 D8.1@1070,322.52
  MidLayer1 w25: v1(988.66,436.34) 1135,582.68 v1(1135,955)
  MidLayer2 w25: v1(830,80) 830,252.24 705,377.24 705,475 755,525 900,525 v1(988.66,436.34)
  Bottom Layer w20: v1(1135,955) 1135,1438.5 C6.1@1160,1463.5
  Bottom Layer w25: v1(830,80) 830,152.72 R12.2@831.06,153.78 ; v1(988.66,436.34) 1000.71,448.39 Q3.3@1070,448.39
NetC6_2: C6.2 R7.2 | length 97
  Bottom Layer w25: C6.2@1160,1526.5 v1(1160,1575) R7.2@1160,1623.5
NetC7_1: C7.1 D5.2 D9.1 Q4.3 R11.2 T1.15 | length 2172.9
  Top Layer w20: T1.15@985,855 v1(985,925)
  Top Layer w25: v1(760,435) D5.2@853.74,435
  Top Layer w50: D9.1@855,321.14 D5.2@855,436.26
  MidLayer1 w25: v1(760,435) 760,700 v1(985,925)
  MidLayer2 w25: v1@761.26,436.26 837.36,436.26 1040,233.62 v1(1040,80)
  Bottom Layer w20: v1(985,925) 985,1445 1005,1465 1063.5,1465 C7.1@1065,1463.5
  Bottom Layer w25: v1(760,435) 852.99,435 Q4.3@865,447.01 ; R11.2@1038.5,155 1038.5,81.5 v1(1040,80)
NetC7_2: C7.2 R8.2 | length 98.3
  Bottom Layer w25: C7.2@1065,1526.5 v1(1065,1575) R8.2@1065,1624.8
NetC8_1: C8.1 D2.1 D3.1 D4.1 D5.1 L3.1 | length 1402.1
  Top Layer w35: v1@1068.7,668.7 v1(1070,670) ; C8.1@1640,303.44 L3.1@1640,381.95 L3.1@1640,405
  Top Layer w50: D5.1@855,593.74 v1(855,670) ; D4.1@1068.62,593.74 D4.1@1068.7,593.82 v1@1068.7,668.7 ; D3.1@1279.92,593.82 D3.1@1280,593.74 v1(1280,670) ; D2.1@1478.74,593.74 D2.1@1480,595 v1(1480,670) ; v1(1600,445) L3.1@1640,405
  Bottom Layer w50: v1(855,670) v1(1070,670) v1(1280,670) v1(1480,670) 1545,670 1600,615 v1(1600,445)
NetC8_2: C8.2 C11.2 C12.2 C13.2 C14.2 D6.2 D7.2 D8.2 D9.2 L4.1 Q1.2 Q2.2 Q3.2 Q4.2 R13.1 R14.1 R15.1 R16.1 | length 1405.8
  Top Layer w25: v1(750,160) 753.66,163.66 D9.2@855,163.66 ; L4.1@1640,161.95 C8.2@1640,240.45
  Top Layer w50: D8.2@1068.62,163.66 D8.2@1070,165.04 ; D7.2@1282.29,165.04 D7.2@1282.45,164.88 ; D6.2@1477.36,164.88 D6.2@1480,167.52 ; D6.2@1485.57,161.95 L4.1@1640,161.95
  Bottom Layer w25: v1(750,160) 750,210 763.7,223.7 C14.2@833.5,223.7 ; v1(970,163.66) 970,215 980.08,225.08 C13.2@1038.5,225.08 ; v1(1180,165.04) 1180,215 1189.92,224.92 C12.2@1250.95,224.92 ; v1(1380,164.88) 1380,215 1391.18,226.18 C11.2@1440.95,226.18
  Bottom Layer w30: Q4.2@827.6,360.39 827.6,299.61 R16.1@833.5,293.7 C14.2@833.5,223.7 ; Q3.2@1032.6,361.77 1032.6,300.98 R15.1@1038.5,295.08 C13.2@1038.5,225.08 ; Q2.2@1245.05,361.61 1245.05,300.83 R14.1@1250.95,294.92 C12.2@1250.95,224.92 ; Q1.2@1435.05,362.87 1435.05,302.09 R13.1@1440.95,296.18 C11.2@1440.95,226.18
NetC10_1: C10.1 R5.1 R6.1 R7.1 R8.1 | length 387.1
  Bottom Layer w35: R8.1@1065,1687.8 1066.3,1686.5 R7.1@1160,1686.5 1206.85,1686.5 ; C10.1@1205,1786.26 1205,1688.35 1206.85,1686.5 ; R5.1@1350,1686.5 1348.7,1687.8 R6.1@1255,1687.8 1253.7,1686.5 1206.85,1686.5
NetC11_1: C11.1 Q1.1 R9.1 R13.2 | length 210.1
  Bottom Layer w30: R9.1@1506.5,156.26 1503.94,158.81 C11.1@1503.94,226.18 R13.2@1503.94,296.18 1509.85,302.09 Q1.1@1509.85,362.87
NetC12_1: C12.1 Q2.1 R10.1 R14.2 | length 210.1
  Bottom Layer w30: R10.1@1311.5,155 1313.94,157.45 C12.1@1313.94,224.92 R14.2@1313.94,294.92 1319.85,300.83 Q2.1@1319.85,361.61
NetC13_1: C13.1 Q3.1 R11.1 R15.2 | length 209.2
  Bottom Layer w30: R11.1@1101.5,155 C13.1@1101.5,225.08 R15.2@1101.5,295.08 1107.4,300.98 Q3.1@1107.4,361.77
NetC14_1: C14.1 Q4.1 R12.1 R16.2 | length 210.1
  Bottom Layer w30: R12.1@894.05,153.78 896.5,156.23 C14.1@896.5,223.7 R16.2@896.5,293.7 902.4,299.61 Q4.1@902.4,360.39
NetC15_2: C15.2 C18.1 C19.1 C20.1 L5.2 R19.2 T2.2 | length 1025.4
  Top Layer w50: L5.2@1764.5,896.5 L5.2@1764.14,896.14 ; R19.2@1859.92,793.23 C20.1@1759.92,793.23 1759.92,891.92 L5.2@1764.14,896.14 ; 2325,890 2249.65,890 T2.2@2244.42,895.23 2243.51,896.14 C19.1@2109.92,896.14 C18.1@1969.92,896.14 L5.2@1764.14,896.14 ; 2415,899.47 v1(2415,1080)
  Bottom Layer w50: v1(2415,1080) C15.2@2491.26,1080
NetC16_1: C16.1 D11.2 Q6.1 R18.2 | length 249.2
  Bottom Layer w25: R18.2@2961.5,1400 C16.1@2961.5,1465 ; Q6.1@2982.4,1332.4 2982.4,1379.09 2967.03,1394.47 D11.2@3082.78,1394.47
NetC16_2: C16.2 R17.1 R18.1 T2.6 | length 378.2
  Top Layer w25: v2(2850,1350) 2895.42,1304.58 T2.6@2895.42,1189.23
  Bottom Layer w25: v2(2850,1350) R18.1@2898.5,1398.5 ; R18.1@2898.5,1400 C16.2@2898.5,1465 R17.1@2898.5,1530
NetC20_2: C20.2 D12.1 R19.1 | length 237.8
  Top Layer w50: C20.2@1759.92,713.23 R19.1@1859.92,713.23 1941.18,713.23 D12.1@1981.18,753.23
NetC21_1: C21.1 C22.1 C23.1 C24.1 C25.1 J4.2 Q5.5 Q5.6 Q5.7 Q5.8 Q5.9 Q7.5 Q7.6 Q7.7 Q7.8 Q7.9 R20.2 R23.2 | length 974.4
  Top Layer w20: C24.1@3089.92,514.72 3138.93,514.72 ; C21.1@3137.32,913.23 C22.1@3137.32,773.23 C23.1@3137.32,633.23 ; C25.1@3159.92,514.72 3138.93,514.72 ; J4.2@3430,648 3415.23,633.23 C23.1@3137.32,633.23 ; C23.1@3137.32,633.23 3137.32,516.33 3138.93,514.72
  Bottom Layer w20: R23.2@3229.92,663.43 3414.57,663.43 J4.2@3430,648
  other v1: 3230,994.45 3285,1035 3285,1090 3285,1145
NetC26_1: C26.1 R20.1
NetC26_2: C26.2 Q5.1 Q5.2 Q5.3 Q6.3 Q7.1 Q7.2 Q7.3 T2.7 | length 276.9
  Top Layer w25: v1(2970,1140) 2985,1155 C26.2@2985,1198.5
  Bottom Layer w25: Q6.3@2907.6,1295 2907.6,1142.6 v1@2967.4,1142.6
  other v1: 2830,1085 2970,1085 2830,1140
NetC27_1: C27.1 C28.1 D13.1 U1.4 | length 2034.9
  Top Layer w10: C27.1@1941.5,325 1949.72,333.23 U1.4@2028.03,333.23 2103.23,333.23 2115,345
  Top Layer w15: 2115,345 2115,550 2160,595 2325,595 2370,550 2495,550 2520,575 2520,1185 2500,1205 2330,1205 2280,1255 v1(2210,1255) v1@2205,1255
  Top Layer w35: C28.1@2185.35,1410 2205,1410 v1@2205,1255
  Bottom Layer w35: D13.1@2205.53,1320 2210,1315.53 v1(2210,1255)
NetC30_1: C30.1 C34.1 R39.2 U1.2 | length 266.1
  Top Layer w10: C30.1@1941.5,395 1952.09,384.41 U1.2@2028.03,384.41
  Top Layer w15: R39.2@1878.5,475 1878.5,465.2 1930,413.7 1930,406.5 C30.1@1941.5,395
  Top Layer w20: C34.1@1815,473.5 1816.5,475 R39.2@1878.5,475 ; C30.1@1941.5,395 C30.1@1945,398.5
NetC31_1: C31.1 C32.1 R31.1 R37.2 U3.4 | length 316.1
  Bottom Layer w15: U3.4@3087.17,519.33 3157.09,519.33 R37.2@3159.92,516.5 ; C32.1@3159.92,600.43 R37.2@3159.92,516.5 ; R31.1@3229.92,470.43 3210.35,490 3186.42,490 R37.2@3159.92,516.5
  Bottom Layer w25: C31.1@3091.42,601.93 3158.43,601.93 C32.1@3159.92,600.43
NetC31_2: C31.2 D15.1 R27.1 R32.2 U2.2 U3.3 | length 659.1
  Top Layer w15: U2.2@2664.92,649.53 2790.47,649.53 2795,645 2870,645 2881.42,633.58 R27.1@2881.42,603.23 ; D15.1@2887.4,492.4 v1(2887.4,554.96) v1@2887.4,559.92
  Top Layer w20: R27.1@2881.42,603.23 2887.32,597.32 2887.32,560 v1@2887.4,559.92
  Bottom Layer w20: v1(2887.4,554.96) v1@2887.4,559.92 ; v1(2887.4,554.96) 2935,555 2970.67,519.33 U3.3@2992.68,519.33 3028.43,555.08 C31.2@3028.43,601.93 R32.2@3028.43,671.93
NetC32_2: C32.2 R32.1 | length 72
  Bottom Layer w25: R32.1@3091.42,671.93 3099.92,663.43 C32.2@3159.92,663.43
NetC33_1: C33.1 D15.3 R26.1 | length 261.1
  Top Layer w25: R26.1@2729.92,443.03 2755.35,417.6 2850,417.6 2944.49,417.6 C33.1@2969.92,443.03
NetC34_2: C34.2 R38.2 | length 65
  Top Layer w20: C34.2@1815,536.5 1875,536.5 R38.2@1878.5,540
